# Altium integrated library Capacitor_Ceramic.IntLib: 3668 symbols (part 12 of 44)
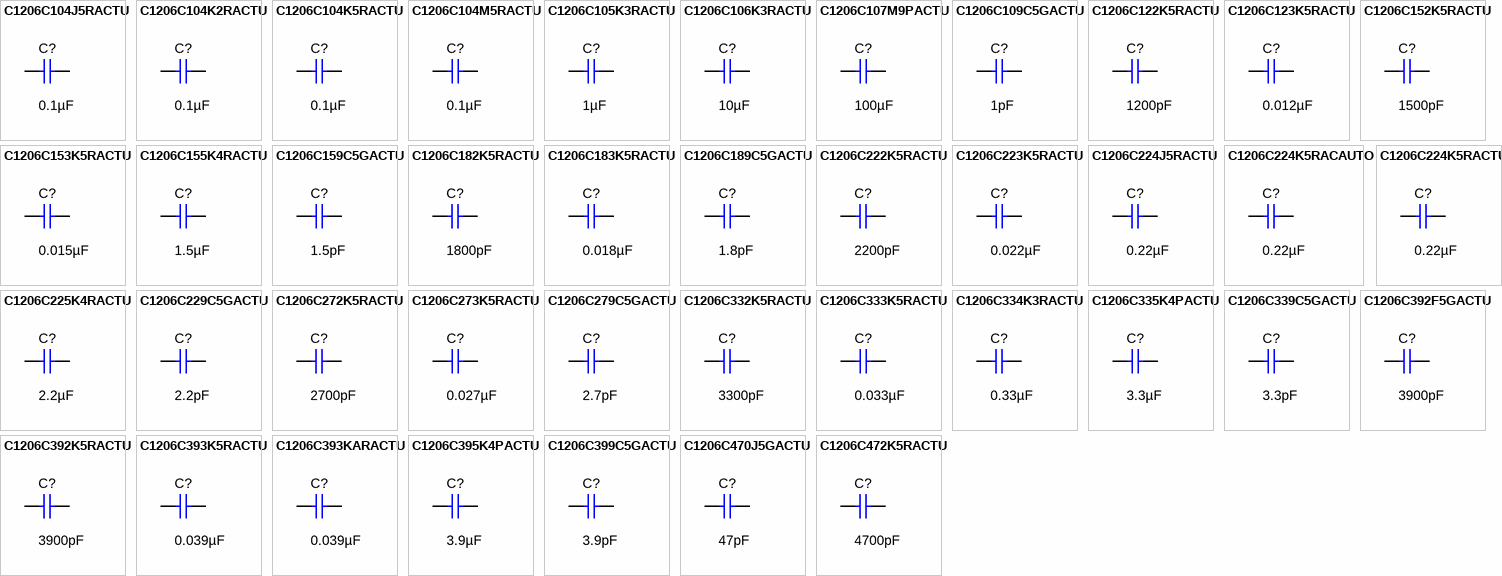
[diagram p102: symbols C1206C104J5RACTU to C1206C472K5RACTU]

## C1206C104K2RACTU
designator C?  ValueDisplayed: 0.1µF  (hidden comment: C1206C104K2RACTU)
CAP, CERM, 0.1 µF, 200 V,+/- 10%, X7R, 1206; Manufacturer: Kemet; Polarized: N; CompType: Capacitor; Value: 0.1uF; U/M: EA; Cap_F: 0.0000001; Tolerance_%: 10; VDC_V: 200; Value2: 200V; TaMin_C: -55; TaMax_C: 125; Cap_Case: 1206; SizeArea_mm2: 5.12; SizeAreaWB_mm2: 10.92; SizeX_mm: 3.2; SizeY_mm: 1.6; SizeZ_mm: 1.35; AEC Category: Q200
signal-integrity model Cap
simulation model Cap
footprint 1206
footprint 1206M
footprint 1206L
pins: 1, 2

## C1206C104K5RACTU
designator C?  ValueDisplayed: 0.1µF  (hidden comment: C1206C104K5RACTU)
CAP, CERM, 0.1 µF, 50 V,+/- 10%, X7R, 1206; Manufacturer: Kemet; Polarized: N; CompType: Capacitor; Value: 0.1uF; U/M: EA; Cap_F: 0.0000001; Tolerance_%: 10; ESR_ohm: 0.059; Value1: 0.059 ohm; VDC_V: 50; Value2: 50V; IRMS_A: 1.2; TaMin_C: -55; TaMax_C: 125; Cap_Case: 1206; SizeArea_mm2: 5.12; SizeAreaWB_mm2: 10.92; SizeX_mm: 3.2; SizeY_mm: 1.6; SizeZ_mm: 1.35; AEC Category: Q200; Green_Lifecycle: Active; Green_REACh: Passed
signal-integrity model Cap
simulation model Cap
footprint 1206
footprint 1206M
footprint 1206L
pins: 1, 2

## C1206C104M5RACTU
designator C?  ValueDisplayed: 0.1µF  (hidden comment: C1206C104M5RACTU)
CAP, CERM, 0.1 µF, 50 V,+/- 20%, X7R, 1206; Manufacturer: Kemet; Polarized: N; CompType: Capacitor; Value: 0.1uF; U/M: EA; Cap_F: 0.0000001; Tolerance_%: 20; ESR_ohm: 0.059; Value1: 0.059 ohm; VDC_V: 50; Value2: 50V; IRMS_A: 1.2; TaMin_C: -55; TaMax_C: 125; Cap_Case: 1206; SizeArea_mm2: 5.12; SizeAreaWB_mm2: 10.92; SizeX_mm: 3.2; SizeY_mm: 1.6; SizeZ_mm: 1.35; AEC Category: Q200; Green_Lifecycle: Active; Green_REACh: Passed
signal-integrity model Cap
simulation model Cap
footprint 1206
footprint 1206M
footprint 1206L
pins: 1, 2

## C1206C105K3RACTU
designator C?  ValueDisplayed: 1µF  (hidden comment: C1206C105K3RACTU)
CAP, CERM, 1 µF, 25 V,+/- 10%, X7R, 1206; Manufacturer: Kemet; Polarized: N; CompType: Capacitor; Value: 1uF; U/M: EA; Cap_F: 0.000001; Tolerance_%: 10; ESR_ohm: 0.011; Value1: 0.011 ohm; VDC_V: 25; Value2: 25V; IRMS_A: 3.55; TaMin_C: -55; TaMax_C: 125; Cap_Case: 1206; SizeArea_mm2: 5.12; SizeAreaWB_mm2: 10.92; SizeX_mm: 3.2; SizeY_mm: 1.6; SizeZ_mm: 1.35; AEC Category: Q200; Green_Lifecycle: Active; Green_REACh: Passed
signal-integrity model Cap
simulation model Cap
footprint 1206
footprint 1206M
footprint 1206L
pins: 1, 2

## C1206C106K3RACTU
designator C?  ValueDisplayed: 10µF  (hidden comment: C1206C106K3RACTU)
CAP, CERM, 10 µF, 25 V,+/- 10%, X7R, 1206; Manufacturer: Kemet; Polarized: N; CompType: Capacitor; Value: 10uF; U/M: EA; Cap_F: 0.00001; Tolerance_%: 10; VDC_V: 25; Value2: 25V; TaMin_C: -55; TaMax_C: 125; Cap_Case: 1206; SizeArea_mm2: 5.12; SizeAreaWB_mm2: 10.92; SizeX_mm: 3.2; SizeY_mm: 1.6; SizeZ_mm: 1.9; AEC Category: Q200; Green_Lifecycle: Active; Green_REACh: Passed
signal-integrity model Cap
simulation model Cap
footprint 1206_190
footprint 1206_190M
footprint 1206_190L
pins: 1, 2

## C1206C107M9PACTU
designator C?  ValueDisplayed: 100µF  (hidden comment: C1206C107M9PACTU)
CAP, CERM, 100 µF, 6.3 V,+/- 20%, X5R, 1206; Manufacturer: Kemet; Polarized: N; CompType: Capacitor; Value: 100uF; U/M: EA; Cap_F: 0.0001; Tolerance_%: 20; VDC_V: 6.3; Value2: 6.3V; TaMin_C: -55; TaMax_C: 85; Cap_Case: 1206; SizeArea_mm2: 5.12; SizeAreaWB_mm2: 10.92; SizeX_mm: 3.2; SizeY_mm: 1.6; SizeZ_mm: 1.9; AEC Category: Q200; Green_Lifecycle: Active; Green_REACh: Passed
signal-integrity model Cap
simulation model Cap
footprint 1206_190
footprint 1206_190M
footprint 1206_190L
pins: 1, 2

## C1206C109C5GACTU
designator C?  ValueDisplayed: 1pF  (hidden comment: C1206C109C5GACTU)
CAP, CERM, 1 pF, 50 V,+/- 25%, C0G/NP0, 1206; Manufacturer: Kemet; Polarized: N; CompType: Capacitor; Value: 1pF; U/M: EA; Cap_F: 0.000000000001; Tolerance_%: 25; ESR_ohm: 0.821; Value1: 0.821 ohm; VDC_V: 50; Value2: 50V; IRMS_A: 0.022; TaMin_C: -55; TaMax_C: 125; Cap_Case: 1206; SizeArea_mm2: 5.12; SizeAreaWB_mm2: 10.92; SizeX_mm: 3.2; SizeY_mm: 1.6; SizeZ_mm: 1.35; AEC Category: Q200; Green_Lifecycle: Not Set; Green_REACh: Incomplete
signal-integrity model Cap
simulation model Cap
footprint 1206
footprint 1206M
footprint 1206L
pins: 1, 2

## C1206C122K5RACTU
designator C?  ValueDisplayed: 1200pF  (hidden comment: C1206C122K5RACTU)
CAP, CERM, 1200 pF, 50 V,+/- 10%, X7R, 1206; Manufacturer: Kemet; Polarized: N; CompType: Capacitor; Value: 1200pF; U/M: EA; Cap_F: 0.0000000012; Tolerance_%: 10; ESR_ohm: 0.604; Value1: 0.604 ohm; VDC_V: 50; Value2: 50V; IRMS_A: 0.164; TaMin_C: -55; TaMax_C: 125; Cap_Case: 1206; SizeArea_mm2: 5.12; SizeAreaWB_mm2: 10.92; SizeX_mm: 3.2; SizeY_mm: 1.6; SizeZ_mm: 1.35; AEC Category: Q200; Green_Lifecycle: Not Set; Green_REACh: Incomplete
signal-integrity model Cap
simulation model Cap
footprint 1206
footprint 1206M
footprint 1206L
pins: 1, 2

## C1206C123K5RACTU
designator C?  ValueDisplayed: 0.012µF  (hidden comment: C1206C123K5RACTU)
CAP, CERM, 0.012 µF, 50 V,+/- 10%, X7R, 1206; Manufacturer: Kemet; Polarized: N; CompType: Capacitor; Value: 0.012uF; U/M: EA; Cap_F: 0.000000012; Tolerance_%: 10; ESR_ohm: 0.136; Value1: 0.136 ohm; VDC_V: 50; Value2: 50V; IRMS_A: 0.475; TaMin_C: -55; TaMax_C: 125; Cap_Case: 1206; SizeArea_mm2: 5.12; SizeAreaWB_mm2: 10.92; SizeX_mm: 3.2; SizeY_mm: 1.6; SizeZ_mm: 1.35; AEC Category: Q200; Green_Lifecycle: Not Set; Green_REACh: Incomplete
signal-integrity model Cap
simulation model Cap
footprint 1206
footprint 1206M
footprint 1206L
pins: 1, 2

## C1206C152K5RACTU
designator C?  ValueDisplayed: 1500pF  (hidden comment: C1206C152K5RACTU)
CAP, CERM, 1500 pF, 50 V,+/- 10%, X7R, 1206; Manufacturer: Kemet; Polarized: N; CompType: Capacitor; Value: 1500pF; U/M: EA; Cap_F: 0.0000000015; Tolerance_%: 10; ESR_ohm: 0.545; Value1: 0.545 ohm; VDC_V: 50; Value2: 50V; IRMS_A: 0.173; TaMin_C: -55; TaMax_C: 125; Cap_Case: 1206; SizeArea_mm2: 5.12; SizeAreaWB_mm2: 10.92; SizeX_mm: 3.2; SizeY_mm: 1.6; SizeZ_mm: 1.35; AEC Category: Q200; Green_Lifecycle: Not Set; Green_REACh: Incomplete
signal-integrity model Cap
simulation model Cap
footprint 1206
footprint 1206M
footprint 1206L
pins: 1, 2

## C1206C153K5RACTU
designator C?  ValueDisplayed: 0.015µF  (hidden comment: C1206C153K5RACTU)
CAP, CERM, 0.015 µF, 50 V,+/- 10%, X7R, 1206; Manufacturer: Kemet; Polarized: N; CompType: Capacitor; Value: 0.015uF; U/M: EA; Cap_F: 0.000000015; Tolerance_%: 10; ESR_ohm: 0.12; Value1: 0.12 ohm; VDC_V: 50; Value2: 50V; IRMS_A: 0.536; TaMin_C: -55; TaMax_C: 125; Cap_Case: 1206; SizeArea_mm2: 5.12; SizeAreaWB_mm2: 10.92; SizeX_mm: 3.2; SizeY_mm: 1.6; SizeZ_mm: 1.35; AEC Category: Q200; Green_Lifecycle: Not Set; Green_REACh: Incomplete
signal-integrity model Cap
simulation model Cap
footprint 1206
footprint 1206M
footprint 1206L
pins: 1, 2

## C1206C155K4RACTU
designator C?  ValueDisplayed: 1.5µF  (hidden comment: C1206C155K4RACTU)
CAP, CERM, 1.5 µF, 16 V,+/- 10%, X7R, 1206; Manufacturer: Kemet; Polarized: N; CompType: Capacitor; Value: 1.5uF; U/M: EA; Cap_F: 0.0000015; Tolerance_%: 10; ESR_ohm: 0.01; Value1: 0.01 ohm; VDC_V: 16; Value2: 16V; IRMS_A: 4.19; TaMin_C: -55; TaMax_C: 125; Cap_Case: 1206; SizeArea_mm2: 5.12; SizeAreaWB_mm2: 10.92; SizeX_mm: 3.2; SizeY_mm: 1.6; SizeZ_mm: 1.35; AEC Category: Q200; Green_Lifecycle: Not Set; Green_REACh: Incomplete
signal-integrity model Cap
simulation model Cap
footprint 1206
footprint 1206M
footprint 1206L
pins: 1, 2

## C1206C159C5GACTU
designator C?  ValueDisplayed: 1.5pF  (hidden comment: C1206C159C5GACTU)
CAP, CERM, 1.5 pF, 50 V,+/- 17%, C0G/NP0, 1206; Manufacturer: Kemet; Polarized: N; CompType: Capacitor; Value: 1.5pF; U/M: EA; Cap_F: 0.0000000000015; Tolerance_%: 17; ESR_ohm: 0.665; Value1: 0.665 ohm; VDC_V: 50; Value2: 50V; IRMS_A: 0.033; TaMin_C: -55; TaMax_C: 125; Cap_Case: 1206; SizeArea_mm2: 5.12; SizeAreaWB_mm2: 10.92; SizeX_mm: 3.2; SizeY_mm: 1.6; SizeZ_mm: 1.35; AEC Category: Q200; Green_Lifecycle: Not Set; Green_REACh: Incomplete
signal-integrity model Cap
simulation model Cap
footprint 1206
footprint 1206M
footprint 1206L
pins: 1, 2

## C1206C182K5RACTU
designator C?  ValueDisplayed: 1800pF  (hidden comment: C1206C182K5RACTU)
CAP, CERM, 1800 pF, 50 V,+/- 10%, X7R, 1206; Manufacturer: Kemet; Polarized: N; CompType: Capacitor; Value: 1800pF; U/M: EA; Cap_F: 0.0000000018; Tolerance_%: 10; ESR_ohm: 0.453; Value1: 0.453 ohm; VDC_V: 50; Value2: 50V; IRMS_A: 0.19; TaMin_C: -55; TaMax_C: 125; Cap_Case: 1206; SizeArea_mm2: 5.12; SizeAreaWB_mm2: 10.92; SizeX_mm: 3.2; SizeY_mm: 1.6; SizeZ_mm: 1.35; AEC Category: Q200; Green_Lifecycle: Not Set; Green_REACh: Incomplete
signal-integrity model Cap
simulation model Cap
footprint 1206
footprint 1206M
footprint 1206L
pins: 1, 2

## C1206C183K5RACTU
designator C?  ValueDisplayed: 0.018µF  (hidden comment: C1206C183K5RACTU)
CAP, CERM, 0.018 µF, 50 V,+/- 10%, X7R, 1206; Manufacturer: Kemet; Polarized: N; CompType: Capacitor; Value: 0.018uF; U/M: EA; Cap_F: 0.000000018; Tolerance_%: 10; ESR_ohm: 0.114; Value1: 0.114 ohm; VDC_V: 50; Value2: 50V; IRMS_A: 0.547; TaMin_C: -55; TaMax_C: 125; Cap_Case: 1206; SizeArea_mm2: 5.12; SizeAreaWB_mm2: 10.92; SizeX_mm: 3.2; SizeY_mm: 1.6; SizeZ_mm: 1.35; AEC Category: Q200; Green_Lifecycle: Not Set; Green_REACh: Incomplete
signal-integrity model Cap
simulation model Cap
footprint 1206
footprint 1206M
footprint 1206L
pins: 1, 2

## C1206C189C5GACTU
designator C?  ValueDisplayed: 1.8pF  (hidden comment: C1206C189C5GACTU)
CAP, CERM, 1.8 pF, 50 V,+/- 14%, C0G/NP0, 1206; Manufacturer: Kemet; Polarized: N; CompType: Capacitor; Value: 1.8pF; U/M: EA; Cap_F: 0.0000000000018; Tolerance_%: 14; ESR_ohm: 0.885; Value1: 0.885 ohm; VDC_V: 50; Value2: 50V; IRMS_A: 0.04; TaMin_C: -55; TaMax_C: 125; Cap_Case: 1206; SizeArea_mm2: 5.12; SizeAreaWB_mm2: 10.92; SizeX_mm: 3.2; SizeY_mm: 1.6; SizeZ_mm: 1.35; AEC Category: Q200; Green_Lifecycle: Not Set; Green_REACh: Incomplete
signal-integrity model Cap
simulation model Cap
footprint 1206
footprint 1206M
footprint 1206L
pins: 1, 2

## C1206C222K5RACTU
designator C?  ValueDisplayed: 2200pF  (hidden comment: C1206C222K5RACTU)
CAP, CERM, 2200 pF, 50 V,+/- 10%, X7R, 1206; Manufacturer: Kemet; Polarized: N; CompType: Capacitor; Value: 2200pF; U/M: EA; Cap_F: 0.0000000022; Tolerance_%: 10; ESR_ohm: 0.41; Value1: 0.41 ohm; VDC_V: 50; Value2: 50V; IRMS_A: 0.199; TaMin_C: -55; TaMax_C: 125; Cap_Case: 1206; SizeArea_mm2: 5.12; SizeAreaWB_mm2: 10.92; SizeX_mm: 3.2; SizeY_mm: 1.6; SizeZ_mm: 1.35; AEC Category: Q200; Green_Lifecycle: Not Set; Green_REACh: Incomplete
signal-integrity model Cap
simulation model Cap
footprint 1206
footprint 1206M
footprint 1206L
pins: 1, 2

## C1206C223K5RACTU
designator C?  ValueDisplayed: 0.022µF  (hidden comment: C1206C223K5RACTU)
CAP, CERM, 0.022 µF, 50 V,+/- 10%, X7R, 1206; Manufacturer: Kemet; Polarized: N; CompType: Capacitor; Value: 0.022uF; U/M: EA; Cap_F: 0.000000022; Tolerance_%: 10; ESR_ohm: 0.104; Value1: 0.104 ohm; VDC_V: 50; Value2: 50V; IRMS_A: 0.633; TaMin_C: -55; TaMax_C: 125; Cap_Case: 1206; SizeArea_mm2: 5.12; SizeAreaWB_mm2: 10.92; SizeX_mm: 3.2; SizeY_mm: 1.6; SizeZ_mm: 1.35; AEC Category: Q200; Green_Lifecycle: Active; Green_REACh: Passed
signal-integrity model Cap
simulation model Cap
footprint 1206
footprint 1206M
footprint 1206L
pins: 1, 2

## C1206C224J5RACTU
designator C?  ValueDisplayed: 0.22µF  (hidden comment: C1206C224J5RACTU)
CAP, CERM, 0.22 µF, 50 V,+/- 5%, X7R, 1206; Manufacturer: Kemet; Polarized: N; CompType: Capacitor; Value: 0.22uF; U/M: EA; Cap_F: 0.00000022; Tolerance_%: 5; ESR_ohm: 0.081; Value1: 0.081 ohm; VDC_V: 50; Value2: 50V; IRMS_A: 1.95; TaMin_C: -55; TaMax_C: 125; Cap_Case: 1206; SizeArea_mm2: 5.12; SizeAreaWB_mm2: 10.92; SizeX_mm: 3.2; SizeY_mm: 1.6; SizeZ_mm: 1.35; AEC Category: Q200; Green_Lifecycle: Not Set; Green_REACh: Incomplete
signal-integrity model Cap
simulation model Cap
footprint 1206
footprint 1206M
footprint 1206L
pins: 1, 2

## C1206C224K5RACAUTO
designator C?  ValueDisplayed: 0.22µF  (hidden comment: C1206C224K5RACAUTO)
CAP, CERM, 0.22 µF, 50 V,+/- 10%, X7R, AEC-Q200 Grade 1, 1206; Manufacturer: Kemet; Polarized: N; CompType: Capacitor; Value: 0.22uF; U/M: EA; Cap_F: 0.00000022; Tolerance_%: 10; VDC_V: 50; Value2: 50V; TaMin_C: -55; TaMax_C: 125; Cap_Case: 1206; SizeArea_mm2: 5.12; SizeAreaWB_mm2: 10.92; SizeX_mm: 3.2; SizeY_mm: 1.6; SizeZ_mm: 1.35; AEC Category: Q200; AEC Qualified: Y; AEC Grade: 1
signal-integrity model Cap
simulation model Cap
footprint 1206
footprint 1206M
footprint 1206L
pins: 1, 2

## C1206C224K5RACTU
designator C?  ValueDisplayed: 0.22µF  (hidden comment: C1206C224K5RACTU)
CAP, CERM, 0.22 µF, 50 V,+/- 10%, X7R, 1206; Manufacturer: Kemet; Polarized: N; CompType: Capacitor; Value: 0.22uF; U/M: EA; Cap_F: 0.00000022; Tolerance_%: 10; ESR_ohm: 0.081; Value1: 0.081 ohm; VDC_V: 50; Value2: 50V; IRMS_A: 1.95; TaMin_C: -55; TaMax_C: 125; Cap_Case: 1206; SizeArea_mm2: 5.12; SizeAreaWB_mm2: 10.92; SizeX_mm: 3.2; SizeY_mm: 1.6; SizeZ_mm: 1.35; AEC Category: Q200; Green_Lifecycle: Not Set; Green_REACh: Incomplete
signal-integrity model Cap
simulation model Cap
footprint 1206
footprint 1206M
footprint 1206L
pins: 1, 2

## C1206C225K4RACTU
designator C?  ValueDisplayed: 2.2µF  (hidden comment: C1206C225K4RACTU)
CAP, CERM, 2.2 µF, 16 V,+/- 10%, X7R, 1206; Manufacturer: Kemet; Polarized: N; CompType: Capacitor; Value: 2.2uF; U/M: EA; Cap_F: 0.0000022; Tolerance_%: 10; ESR_ohm: 0.009; Value1: 0.009 ohm; VDC_V: 16; Value2: 16V; IRMS_A: 4.46; TaMin_C: -55; TaMax_C: 125; Cap_Case: 1206; SizeArea_mm2: 5.12; SizeAreaWB_mm2: 10.92; SizeX_mm: 3.2; SizeY_mm: 1.6; SizeZ_mm: 1.35; AEC Category: Q200; Green_Lifecycle: Not Set; Green_REACh: Incomplete
signal-integrity model Cap
simulation model Cap
footprint 1206
footprint 1206M
footprint 1206L
pins: 1, 2

## C1206C229C5GACTU
designator C?  ValueDisplayed: 2.2pF  (hidden comment: C1206C229C5GACTU)
CAP, CERM, 2.2 pF, 50 V,+/- 11%, C0G/NP0, 1206; Manufacturer: Kemet; Polarized: N; CompType: Capacitor; Value: 2.2pF; U/M: EA; Cap_F: 0.0000000000022; Tolerance_%: 11; ESR_ohm: 0.546; Value1: 0.546 ohm; VDC_V: 50; Value2: 50V; IRMS_A: 0.049; TaMin_C: -55; TaMax_C: 125; Cap_Case: 1206; SizeArea_mm2: 5.12; SizeAreaWB_mm2: 10.92; SizeX_mm: 3.2; SizeY_mm: 1.6; SizeZ_mm: 1.35; AEC Category: Q200; Green_Lifecycle: Not Set; Green_REACh: Incomplete
signal-integrity model Cap
simulation model Cap
footprint 1206
footprint 1206M
footprint 1206L
pins: 1, 2

## C1206C272K5RACTU
designator C?  ValueDisplayed: 2700pF  (hidden comment: C1206C272K5RACTU)
CAP, CERM, 2700 pF, 50 V,+/- 10%, X7R, 1206; Manufacturer: Kemet; Polarized: N; CompType: Capacitor; Value: 2700pF; U/M: EA; Cap_F: 0.0000000027; Tolerance_%: 10; ESR_ohm: 0.378; Value1: 0.378 ohm; VDC_V: 50; Value2: 50V; IRMS_A: 0.232; TaMin_C: -55; TaMax_C: 125; Cap_Case: 1206; SizeArea_mm2: 5.12; SizeAreaWB_mm2: 10.92; SizeX_mm: 3.2; SizeY_mm: 1.6; SizeZ_mm: 1.35; AEC Category: Q200; Green_Lifecycle: Not Set; Green_REACh: Incomplete
signal-integrity model Cap
simulation model Cap
footprint 1206
footprint 1206M
footprint 1206L
pins: 1, 2

## C1206C273K5RACTU
designator C?  ValueDisplayed: 0.027µF  (hidden comment: C1206C273K5RACTU)
CAP, CERM, 0.027 µF, 50 V,+/- 10%, X7R, 1206; Manufacturer: Kemet; Polarized: N; CompType: Capacitor; Value: 0.027uF; U/M: EA; Cap_F: 0.000000027; Tolerance_%: 10; ESR_ohm: 0.095; Value1: 0.095 ohm; VDC_V: 50; Value2: 50V; IRMS_A: 0.765; TaMin_C: -55; TaMax_C: 125; Cap_Case: 1206; SizeArea_mm2: 5.12; SizeAreaWB_mm2: 10.92; SizeX_mm: 3.2; SizeY_mm: 1.6; SizeZ_mm: 1.35; AEC Category: Q200; Green_Lifecycle: Not Set; Green_REACh: Incomplete
signal-integrity model Cap
simulation model Cap
footprint 1206
footprint 1206M
footprint 1206L
pins: 1, 2

## C1206C279C5GACTU
designator C?  ValueDisplayed: 2.7pF  (hidden comment: C1206C279C5GACTU)
CAP, CERM, 2.7 pF, 50 V,+/- 9%, C0G/NP0, 1206; Manufacturer: Kemet; Polarized: N; CompType: Capacitor; Value: 2.7pF; U/M: EA; Cap_F: 0.0000000000027; Tolerance_%: 9; ESR_ohm: 0.492; Value1: 0.492 ohm; VDC_V: 50; Value2: 50V; IRMS_A: 0.06; TaMin_C: -55; TaMax_C: 125; Cap_Case: 1206; SizeArea_mm2: 5.12; SizeAreaWB_mm2: 10.92; SizeX_mm: 3.2; SizeY_mm: 1.6; SizeZ_mm: 1.35; AEC Category: Q200; Green_Lifecycle: Not Set; Green_REACh: Incomplete
signal-integrity model Cap
simulation model Cap
footprint 1206
footprint 1206M
footprint 1206L
pins: 1, 2

## C1206C332K5RACTU
designator C?  ValueDisplayed: 3300pF  (hidden comment: C1206C332K5RACTU)
CAP, CERM, 3300 pF, 50 V,+/- 10%, X7R, 1206; Manufacturer: Kemet; Polarized: N; CompType: Capacitor; Value: 3300pF; U/M: EA; Cap_F: 0.0000000033; Tolerance_%: 10; ESR_ohm: 0.336; Value1: 0.336 ohm; VDC_V: 50; Value2: 50V; IRMS_A: 0.27; TaMin_C: -55; TaMax_C: 125; Cap_Case: 1206; SizeArea_mm2: 5.12; SizeAreaWB_mm2: 10.92; SizeX_mm: 3.2; SizeY_mm: 1.6; SizeZ_mm: 1.35; AEC Category: Q200; Green_Lifecycle: Not Set; Green_REACh: Incomplete
signal-integrity model Cap
simulation model Cap
footprint 1206
footprint 1206M
footprint 1206L
pins: 1, 2

## C1206C333K5RACTU
designator C?  ValueDisplayed: 0.033µF  (hidden comment: C1206C333K5RACTU)
CAP, CERM, 0.033 µF, 50 V,+/- 10%, X7R, 1206; Manufacturer: Kemet; Polarized: N; CompType: Capacitor; Value: 0.033uF; U/M: EA; Cap_F: 0.000000033; Tolerance_%: 10; ESR_ohm: 0.089; Value1: 0.089 ohm; VDC_V: 50; Value2: 50V; IRMS_A: 0.822; TaMin_C: -55; TaMax_C: 125; Cap_Case: 1206; SizeArea_mm2: 5.12; SizeAreaWB_mm2: 10.92; SizeX_mm: 3.2; SizeY_mm: 1.6; SizeZ_mm: 1.35; AEC Category: Q200; Green_Lifecycle: Not Set; Green_REACh: Incomplete
signal-integrity model Cap
simulation model Cap
footprint 1206
footprint 1206M
footprint 1206L
pins: 1, 2

## C1206C334K3RACTU
designator C?  ValueDisplayed: 0.33µF  (hidden comment: C1206C334K3RACTU)
CAP, CERM, 0.33 µF, 25 V,+/- 10%, X7R, 1206; Manufacturer: Kemet; Polarized: N; CompType: Capacitor; Value: 0.33uF; U/M: EA; Cap_F: 0.00000033; Tolerance_%: 10; ESR_ohm: 0.07; Value1: 0.07 ohm; VDC_V: 25; Value2: 25V; IRMS_A: 0.905; TaMin_C: -55; TaMax_C: 125; Cap_Case: 1206; SizeArea_mm2: 5.12; SizeAreaWB_mm2: 10.92; SizeX_mm: 3.2; SizeY_mm: 1.6; SizeZ_mm: 1.35; AEC Category: Q200; Green_Lifecycle: Not Set; Green_REACh: Incomplete
signal-integrity model Cap
simulation model Cap
footprint 1206
footprint 1206M
footprint 1206L
pins: 1, 2

## C1206C335K4PACTU
designator C?  ValueDisplayed: 3.3µF  (hidden comment: C1206C335K4PACTU)
CAP, CERM, 3.3 µF, 16 V,+/- 10%, X5R, 1206; Manufacturer: Kemet; Polarized: N; CompType: Capacitor; Value: 3.3uF; U/M: EA; Cap_F: 0.0000033; Tolerance_%: 10; ESR_ohm: 0.011; Value1: 0.011 ohm; VDC_V: 16; Value2: 16V; IRMS_A: 5.25; TaMin_C: -55; TaMax_C: 85; Cap_Case: 1206; SizeArea_mm2: 5.12; SizeAreaWB_mm2: 10.92; SizeX_mm: 3.2; SizeY_mm: 1.6; SizeZ_mm: 1.35; AEC Category: Q200; Green_Lifecycle: Not Set; Green_REACh: Incomplete
signal-integrity model Cap
simulation model Cap
footprint 1206
footprint 1206M
footprint 1206L
pins: 1, 2

## C1206C339C5GACTU
designator C?  ValueDisplayed: 3.3pF  (hidden comment: C1206C339C5GACTU)
CAP, CERM, 3.3 pF, 50 V,+/- 8%, C0G/NP0, 1206; Manufacturer: Kemet; Polarized: N; CompType: Capacitor; Value: 3.3pF; U/M: EA; Cap_F: 0.0000000000033; Tolerance_%: 8; ESR_ohm: 0.444; Value1: 0.444 ohm; VDC_V: 50; Value2: 50V; IRMS_A: 0.073; TaMin_C: -55; TaMax_C: 125; Cap_Case: 1206; SizeArea_mm2: 5.12; SizeAreaWB_mm2: 10.92; SizeX_mm: 3.2; SizeY_mm: 1.6; SizeZ_mm: 1.35; AEC Category: Q200; Green_Lifecycle: Not Set; Green_REACh: Incomplete
signal-integrity model Cap
simulation model Cap
footprint 1206
footprint 1206M
footprint 1206L
pins: 1, 2

## C1206C392F5GACTU
designator C?  ValueDisplayed: 3900pF  (hidden comment: C1206C392F5GACTU)
CAP, CERM, 3900 pF, 50 V,+/- 1%, C0G/NP0, 1206; Manufacturer: Kemet; Polarized: N; CompType: Capacitor; Value: 3900pF; U/M: EA; Cap_F: 0.0000000039; Tolerance_%: 1; VDC_V: 50; Value2: 50V; TaMin_C: -55; TaMax_C: 125; Cap_Case: 1206; SizeArea_mm2: 5.12; SizeAreaWB_mm2: 10.92; SizeX_mm: 3.2; SizeY_mm: 1.6; SizeZ_mm: 1.35; AEC Category: Q200; Green_Lifecycle: Not Set; Green_REACh: Incomplete
signal-integrity model Cap
simulation model Cap
footprint 1206
footprint 1206M
footprint 1206L
pins: 1, 2

## C1206C392K5RACTU
designator C?  ValueDisplayed: 3900pF  (hidden comment: C1206C392K5RACTU)
CAP, CERM, 3900 pF, 50 V,+/- 10%, X7R, 1206; Manufacturer: Kemet; Polarized: N; CompType: Capacitor; Value: 3900pF; U/M: EA; Cap_F: 0.0000000039; Tolerance_%: 10; ESR_ohm: 0.314; Value1: 0.314 ohm; VDC_V: 50; Value2: 50V; IRMS_A: 0.3; TaMin_C: -55; TaMax_C: 125; Cap_Case: 1206; SizeArea_mm2: 5.12; SizeAreaWB_mm2: 10.92; SizeX_mm: 3.2; SizeY_mm: 1.6; SizeZ_mm: 1.35; AEC Category: Q200; Green_Lifecycle: Not Set; Green_REACh: Incomplete
signal-integrity model Cap
simulation model Cap
footprint 1206
footprint 1206M
footprint 1206L
pins: 1, 2

## C1206C393K5RACTU
designator C?  ValueDisplayed: 0.039µF  (hidden comment: C1206C393K5RACTU)
CAP, CERM, 0.039 µF, 50 V,+/- 10%, X7R, 1206; Manufacturer: Kemet; Polarized: N; CompType: Capacitor; Value: 0.039uF; U/M: EA; Cap_F: 0.000000039; Tolerance_%: 10; ESR_ohm: 0.084; Value1: 0.084 ohm; VDC_V: 50; Value2: 50V; IRMS_A: 0.925; TaMin_C: -55; TaMax_C: 125; Cap_Case: 1206; SizeArea_mm2: 5.12; SizeAreaWB_mm2: 10.92; SizeX_mm: 3.2; SizeY_mm: 1.6; SizeZ_mm: 1.35; AEC Category: Q200; Green_Lifecycle: Not Set; Green_REACh: Incomplete
signal-integrity model Cap
simulation model Cap
footprint 1206
footprint 1206M
footprint 1206L
pins: 1, 2

## C1206C393KARACTU
designator C?  ValueDisplayed: 0.039µF  (hidden comment: C1206C393KARACTU)
CAP, CERM, 0.039 µF, 250 V,+/- 10%, X7R, 1206; Manufacturer: Kemet; Polarized: N; CompType: Capacitor; Value: 0.039uF; U/M: EA; Cap_F: 0.000000039; Tolerance_%: 10; VDC_V: 250; Value2: 250V; TaMin_C: -55; TaMax_C: 125; Cap_Case: 1206; SizeArea_mm2: 5.12; SizeAreaWB_mm2: 10.92; SizeX_mm: 3.2; SizeY_mm: 1.6; SizeZ_mm: 1.35; AEC Category: Q200
signal-integrity model Cap
simulation model Cap
footprint 1206
footprint 1206M
footprint 1206L
pins: 1, 2

## C1206C395K4PACTU
designator C?  ValueDisplayed: 3.9µF  (hidden comment: C1206C395K4PACTU)
CAP, CERM, 3.9 µF, 16 V,+/- 10%, X5R, 1206; Manufacturer: Kemet; Polarized: N; CompType: Capacitor; Value: 3.9uF; U/M: EA; Cap_F: 0.0000039; Tolerance_%: 10; ESR_ohm: 0.012; Value1: 0.012 ohm; VDC_V: 16; Value2: 16V; IRMS_A: 5.05; TaMin_C: -55; TaMax_C: 85; Cap_Case: 1206; SizeArea_mm2: 5.12; SizeAreaWB_mm2: 10.92; SizeX_mm: 3.2; SizeY_mm: 1.6; SizeZ_mm: 1.35; AEC Category: Q200; Green_Lifecycle: Not Set; Green_REACh: Incomplete
signal-integrity model Cap
simulation model Cap
footprint 1206
footprint 1206M
footprint 1206L
pins: 1, 2

## C1206C399C5GACTU
designator C?  ValueDisplayed: 3.9pF  (hidden comment: C1206C399C5GACTU)
CAP, CERM, 3.9 pF, 50 V,+/- 6%, C0G/NP0, 1206; Manufacturer: Kemet; Polarized: N; CompType: Capacitor; Value: 3.9pF; U/M: EA; Cap_F: 0.0000000000039; Tolerance_%: 6; ESR_ohm: 0.407; Value1: 0.407 ohm; VDC_V: 50; Value2: 50V; IRMS_A: 0.086; TaMin_C: -55; TaMax_C: 125; Cap_Case: 1206; SizeArea_mm2: 5.12; SizeAreaWB_mm2: 10.92; SizeX_mm: 3.2; SizeY_mm: 1.6; SizeZ_mm: 1.35; AEC Category: Q200; Green_Lifecycle: Not Set; Green_REACh: Incomplete
signal-integrity model Cap
simulation model Cap
footprint 1206
footprint 1206M
footprint 1206L
pins: 1, 2

## C1206C470J5GACTU
designator C?  ValueDisplayed: 47pF  (hidden comment: C1206C470J5GACTU)
CAP, CERM, 47 pF, 50 V,+/- 5%, C0G/NP0, 1206; Manufacturer: Kemet; Polarized: N; CompType: Capacitor; Value: 47pF; U/M: EA; Cap_F: 0.000000000047; Tolerance_%: 5; VDC_V: 50; Value2: 50V; TaMin_C: -55; TaMax_C: 125; Cap_Case: 1206; SizeArea_mm2: 5.12; SizeAreaWB_mm2: 10.92; SizeX_mm: 3.2; SizeY_mm: 1.6; SizeZ_mm: 1.35; AEC Category: Q200; Green_Lifecycle: Not Set; Green_REACh: Incomplete
signal-integrity model Cap
simulation model Cap
footprint 1206
footprint 1206M
footprint 1206L
pins: 1, 2

## C1206C472K5RACTU
designator C?  ValueDisplayed: 4700pF  (hidden comment: C1206C472K5RACTU)
CAP, CERM, 4700 pF, 50 V,+/- 10%, X7R, 1206; Manufacturer: Kemet; Polarized: N; CompType: Capacitor; Value: 4700pF; U/M: EA; Cap_F: 0.0000000047; Tolerance_%: 10; ESR_ohm: 0.234; Value1: 0.234 ohm; VDC_V: 50; Value2: 50V; IRMS_A: 0.29; TaMin_C: -55; TaMax_C: 125; Cap_Case: 1206; SizeArea_mm2: 5.12; SizeAreaWB_mm2: 10.92; SizeX_mm: 3.2; SizeY_mm: 1.6; SizeZ_mm: 1.35; AEC Category: Q200; Green_Lifecycle: Active; Green_REACh: Passed
signal-integrity model Cap
simulation model Cap
footprint 1206
footprint 1206M
footprint 1206L
pins: 1, 2

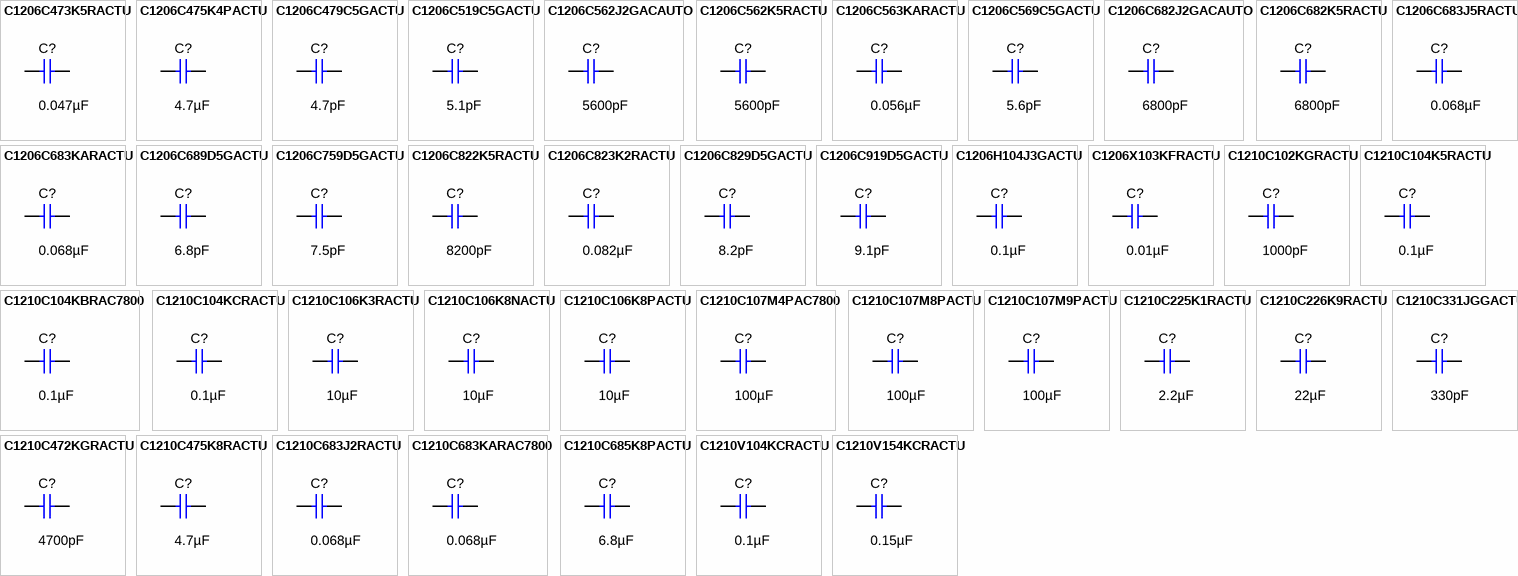
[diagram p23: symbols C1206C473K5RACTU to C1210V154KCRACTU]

## C1206C473K5RACTU
designator C?  ValueDisplayed: 0.047µF  (hidden comment: C1206C473K5RACTU)
CAP, CERM, 0.047 µF, 50 V,+/- 10%, X7R, 1206; Manufacturer: Kemet; Polarized: N; CompType: Capacitor; Value: 0.047uF; U/M: EA; Cap_F: 0.000000047; Tolerance_%: 10; ESR_ohm: 0.076; Value1: 0.076 ohm; VDC_V: 50; Value2: 50V; IRMS_A: 1.14; TaMin_C: -55; TaMax_C: 125; Cap_Case: 1206; SizeArea_mm2: 5.12; SizeAreaWB_mm2: 10.92; SizeX_mm: 3.2; SizeY_mm: 1.6; SizeZ_mm: 1.35; AEC Category: Q200; Green_Lifecycle: Not Set; Green_REACh: Incomplete
signal-integrity model Cap
simulation model Cap
footprint 1206
footprint 1206M
footprint 1206L
pins: 1, 2

## C1206C475K4PACTU
designator C?  ValueDisplayed: 4.7µF  (hidden comment: C1206C475K4PACTU)
CAP, CERM, 4.7 µF, 16 V,+/- 10%, X5R, 1206; Manufacturer: Kemet; Polarized: N; CompType: Capacitor; Value: 4.7uF; U/M: EA; Cap_F: 0.0000047; Tolerance_%: 10; ESR_ohm: 0.013; Value1: 0.013 ohm; VDC_V: 16; Value2: 16V; IRMS_A: 4.9; TaMin_C: -55; TaMax_C: 85; Cap_Case: 1206; SizeArea_mm2: 5.12; SizeAreaWB_mm2: 10.92; SizeX_mm: 3.2; SizeY_mm: 1.6; SizeZ_mm: 1.35; AEC Category: Q200; Green_Lifecycle: Active; Green_REACh: Passed
signal-integrity model Cap
simulation model Cap
footprint 1206
footprint 1206M
footprint 1206L
pins: 1, 2

## C1206C479C5GACTU
designator C?  ValueDisplayed: 4.7pF  (hidden comment: C1206C479C5GACTU)
CAP, CERM, 4.7 pF, 50 V,+/- 5%, C0G/NP0, 1206; Manufacturer: Kemet; Polarized: N; CompType: Capacitor; Value: 4.7pF; U/M: EA; Cap_F: 0.0000000000047; Tolerance_%: 5; ESR_ohm: 0.37; Value1: 0.37 ohm; VDC_V: 50; Value2: 50V; IRMS_A: 0.104; TaMin_C: -55; TaMax_C: 125; Cap_Case: 1206; SizeArea_mm2: 5.12; SizeAreaWB_mm2: 10.92; SizeX_mm: 3.2; SizeY_mm: 1.6; SizeZ_mm: 1.35; AEC Category: Q200; Green_Lifecycle: Not Set; Green_REACh: Incomplete
signal-integrity model Cap
simulation model Cap
footprint 1206
footprint 1206M
footprint 1206L
pins: 1, 2

## C1206C519C5GACTU
designator C?  ValueDisplayed: 5.1pF  (hidden comment: C1206C519C5GACTU)
CAP, CERM, 5.1 pF, 50 V,+/- 5%, C0G/NP0, 1206; Manufacturer: Kemet; Polarized: N; CompType: Capacitor; Value: 5.1pF; U/M: EA; Cap_F: 0.0000000000051; Tolerance_%: 5; ESR_ohm: 0.354; Value1: 0.354 ohm; VDC_V: 50; Value2: 50V; IRMS_A: 0.113; TaMin_C: -55; TaMax_C: 125; Cap_Case: 1206; SizeArea_mm2: 5.12; SizeAreaWB_mm2: 10.92; SizeX_mm: 3.2; SizeY_mm: 1.6; SizeZ_mm: 1.35; AEC Category: Q200; Green_Lifecycle: Not Set; Green_REACh: Incomplete
signal-integrity model Cap
simulation model Cap
footprint 1206
footprint 1206M
footprint 1206L
pins: 1, 2

## C1206C562J2GACAUTO
designator C?  ValueDisplayed: 5600pF  (hidden comment: C1206C562J2GACAUTO)
CAP, CERM, 5600 pF, 200 V,+/- 5%, C0G/NP0, AEC-Q200 Grade 1, 1206; Manufacturer: Kemet; Polarized: N; CompType: Capacitor; Value: 5600pF; U/M: EA; Cap_F: 0.0000000056; Tolerance_%: 5; VDC_V: 200; Value2: 200V; TaMin_C: -55; TaMax_C: 125; Cap_Case: 1206; SizeArea_mm2: 5.12; SizeAreaWB_mm2: 10.92; SizeX_mm: 3.2; SizeY_mm: 1.6; SizeZ_mm: 1.35; AEC Category: Q200; AEC Qualified: Y; AEC Grade: 1; Green_Lifecycle: Not Set; Green_REACh: Incomplete
signal-integrity model Cap
simulation model Cap
footprint 1206
footprint 1206M
footprint 1206L
pins: 1, 2

## C1206C562K5RACTU
designator C?  ValueDisplayed: 5600pF  (hidden comment: C1206C562K5RACTU)
CAP, CERM, 5600 pF, 50 V,+/- 10%, X7R, 1206; Manufacturer: Kemet; Polarized: N; CompType: Capacitor; Value: 5600pF; U/M: EA; Cap_F: 0.0000000056; Tolerance_%: 10; ESR_ohm: 0.221; Value1: 0.221 ohm; VDC_V: 50; Value2: 50V; IRMS_A: 0.326; TaMin_C: -55; TaMax_C: 125; Cap_Case: 1206; SizeArea_mm2: 5.12; SizeAreaWB_mm2: 10.92; SizeX_mm: 3.2; SizeY_mm: 1.6; SizeZ_mm: 1.35; AEC Category: Q200; Green_Lifecycle: Not Set; Green_REACh: Incomplete
signal-integrity model Cap
simulation model Cap
footprint 1206
footprint 1206M
footprint 1206L
pins: 1, 2

## C1206C563KARACTU
designator C?  ValueDisplayed: 0.056µF  (hidden comment: C1206C563KARACTU)
CAP, CERM, 0.056 µF, 250 V,+/- 10%, X7R, 1206; Manufacturer: Kemet; Polarized: N; CompType: Capacitor; Value: 0.056uF; U/M: EA; Cap_F: 0.000000056; Tolerance_%: 10; VDC_V: 250; Value2: 250V; TaMin_C: -55; TaMax_C: 125; Cap_Case: 1206; SizeArea_mm2: 5.12; SizeAreaWB_mm2: 10.92; SizeX_mm: 3.2; SizeY_mm: 1.6; SizeZ_mm: 1.35; AEC Category: Q200; Green_Lifecycle: Not Set; Green_REACh: Incomplete
signal-integrity model Cap
simulation model Cap
footprint 1206
footprint 1206M
footprint 1206L
pins: 1, 2

## C1206C569C5GACTU
designator C?  ValueDisplayed: 5.6pF  (hidden comment: C1206C569C5GACTU)
CAP, CERM, 5.6 pF, 50 V,+/- 4%, C0G/NP0, 1206; Manufacturer: Kemet; Polarized: N; CompType: Capacitor; Value: 5.6pF; U/M: EA; Cap_F: 0.0000000000056; Tolerance_%: 4; ESR_ohm: 0.339; Value1: 0.339 ohm; VDC_V: 50; Value2: 50V; IRMS_A: 0.123; TaMin_C: -55; TaMax_C: 125; Cap_Case: 1206; SizeArea_mm2: 5.12; SizeAreaWB_mm2: 10.92; SizeX_mm: 3.2; SizeY_mm: 1.6; SizeZ_mm: 1.35; AEC Category: Q200; Green_Lifecycle: Not Set; Green_REACh: Incomplete
signal-integrity model Cap
simulation model Cap
footprint 1206
footprint 1206M
footprint 1206L
pins: 1, 2

## C1206C682J2GACAUTO
designator C?  ValueDisplayed: 6800pF  (hidden comment: C1206C682J2GACAUTO)
CAP, CERM, 6800 pF, 200 V,+/- 5%, C0G/NP0, AEC-Q200 Grade 1, 1206; Manufacturer: Kemet; Polarized: N; CompType: Capacitor; Value: 6800pF; U/M: EA; Cap_F: 0.0000000068; Tolerance_%: 5; VDC_V: 200; Value2: 200V; TaMin_C: -55; TaMax_C: 125; Cap_Case: 1206; SizeArea_mm2: 5.12; SizeAreaWB_mm2: 10.92; SizeX_mm: 3.2; SizeY_mm: 1.6; SizeZ_mm: 1.35; AEC Category: Q200; AEC Qualified: Y; AEC Grade: 1; Green_Lifecycle: Not Set; Green_REACh: Incomplete
signal-integrity model Cap
simulation model Cap
footprint 1206
footprint 1206M
footprint 1206L
pins: 1, 2

## C1206C682K5RACTU
designator C?  ValueDisplayed: 6800pF  (hidden comment: C1206C682K5RACTU)
CAP, CERM, 6800 pF, 50 V,+/- 10%, X7R, 1206; Manufacturer: Kemet; Polarized: N; CompType: Capacitor; Value: 6800pF; U/M: EA; Cap_F: 0.0000000068; Tolerance_%: 10; ESR_ohm: 0.203; Value1: 0.203 ohm; VDC_V: 50; Value2: 50V; IRMS_A: 0.368; TaMin_C: -55; TaMax_C: 125; Cap_Case: 1206; SizeArea_mm2: 5.12; SizeAreaWB_mm2: 10.92; SizeX_mm: 3.2; SizeY_mm: 1.6; SizeZ_mm: 1.35; AEC Category: Q200; Green_Lifecycle: Not Set; Green_REACh: Incomplete
signal-integrity model Cap
simulation model Cap
footprint 1206
footprint 1206M
footprint 1206L
pins: 1, 2

## C1206C683J5RACTU
designator C?  ValueDisplayed: 0.068µF  (hidden comment: C1206C683J5RACTU)
CAP, CERM, 0.068 µF, 50 V,+/- 5%, X7R, 1206; Manufacturer: Kemet; Polarized: N; CompType: Capacitor; Value: 0.068uF; U/M: EA; Cap_F: 0.000000068; Tolerance_%: 5; ESR_ohm: 0.067; Value1: 0.067 ohm; VDC_V: 50; Value2: 50V; IRMS_A: 1.06; TaMin_C: -55; TaMax_C: 125; Cap_Case: 1206; SizeArea_mm2: 5.12; SizeAreaWB_mm2: 10.92; SizeX_mm: 3.2; SizeY_mm: 1.6; SizeZ_mm: 1.35; AEC Category: Q200; Green_Lifecycle: Not Set; Green_REACh: Incomplete
signal-integrity model Cap
simulation model Cap
footprint 1206
footprint 1206M
footprint 1206L
pins: 1, 2

## C1206C683KARACTU
designator C?  ValueDisplayed: 0.068µF  (hidden comment: C1206C683KARACTU)
CAP, CERM, 0.068 µF, 250 V,+/- 10%, X7R, 1206; Manufacturer: Kemet; Polarized: N; CompType: Capacitor; Value: 0.068uF; U/M: EA; Cap_F: 0.000000068; Tolerance_%: 10; VDC_V: 250; Value2: 250V; TaMin_C: -55; TaMax_C: 125; Cap_Case: 1206; SizeArea_mm2: 5.12; SizeAreaWB_mm2: 10.92; SizeX_mm: 3.2; SizeY_mm: 1.6; SizeZ_mm: 1.35; AEC Category: Q200; Green_Lifecycle: Not Set; Green_REACh: Incomplete
signal-integrity model Cap
simulation model Cap
footprint 1206
footprint 1206M
footprint 1206L
pins: 1, 2

## C1206C689D5GACTU
designator C?  ValueDisplayed: 6.8pF  (hidden comment: C1206C689D5GACTU)
CAP, CERM, 6.8 pF, 50 V,+/- 7%, C0G/NP0, 1206; Manufacturer: Kemet; Polarized: N; CompType: Capacitor; Value: 6.8pF; U/M: EA; Cap_F: 0.0000000000068; Tolerance_%: 7; ESR_ohm: 0.307; Value1: 0.307 ohm; VDC_V: 50; Value2: 50V; IRMS_A: 0.15; TaMin_C: -55; TaMax_C: 125; Cap_Case: 1206; SizeArea_mm2: 5.12; SizeAreaWB_mm2: 10.92; SizeX_mm: 3.2; SizeY_mm: 1.6; SizeZ_mm: 1.35; AEC Category: Q200; Green_Lifecycle: Not Set; Green_REACh: Incomplete
signal-integrity model Cap
simulation model Cap
footprint 1206
footprint 1206M
footprint 1206L
pins: 1, 2

## C1206C759D5GACTU
designator C?  ValueDisplayed: 7.5pF  (hidden comment: C1206C759D5GACTU)
CAP, CERM, 7.5 pF, 50 V,+/- 7%, C0G/NP0, 1206; Manufacturer: Kemet; Polarized: N; CompType: Capacitor; Value: 7.5pF; U/M: EA; Cap_F: 0.0000000000075; Tolerance_%: 7; ESR_ohm: 0.292; Value1: 0.292 ohm; VDC_V: 50; Value2: 50V; IRMS_A: 0.166; TaMin_C: -55; TaMax_C: 125; Cap_Case: 1206; SizeArea_mm2: 5.12; SizeAreaWB_mm2: 10.92; SizeX_mm: 3.2; SizeY_mm: 1.6; SizeZ_mm: 1.35; AEC Category: Q200; Green_Lifecycle: Not Set; Green_REACh: Incomplete
signal-integrity model Cap
simulation model Cap
footprint 1206
footprint 1206M
footprint 1206L
pins: 1, 2

## C1206C822K5RACTU
designator C?  ValueDisplayed: 8200pF  (hidden comment: C1206C822K5RACTU)
CAP, CERM, 8200 pF, 50 V,+/- 10%, X7R, 1206; Manufacturer: Kemet; Polarized: N; CompType: Capacitor; Value: 8200pF; U/M: EA; Cap_F: 0.0000000082; Tolerance_%: 10; ESR_ohm: 0.184; Value1: 0.184 ohm; VDC_V: 50; Value2: 50V; IRMS_A: 0.437; TaMin_C: -55; TaMax_C: 125; Cap_Case: 1206; SizeArea_mm2: 5.12; SizeAreaWB_mm2: 10.92; SizeX_mm: 3.2; SizeY_mm: 1.6; SizeZ_mm: 1.35; AEC Category: Q200; Green_Lifecycle: Not Set; Green_REACh: Incomplete
signal-integrity model Cap
simulation model Cap
footprint 1206
footprint 1206M
footprint 1206L
pins: 1, 2

## C1206C823K2RACTU
designator C?  ValueDisplayed: 0.082µF  (hidden comment: C1206C823K2RACTU)
CAP, CERM, 0.082 µF, 200 V,+/- 10%, X7R, 1206; Manufacturer: Kemet; Polarized: N; CompType: Capacitor; Value: 0.082uF; U/M: EA; Cap_F: 0.000000082; Tolerance_%: 10; VDC_V: 200; Value2: 200V; TaMin_C: -55; TaMax_C: 125; Cap_Case: 1206; SizeArea_mm2: 5.12; SizeAreaWB_mm2: 10.92; SizeX_mm: 3.2; SizeY_mm: 1.6; SizeZ_mm: 1.35; AEC Category: Q200
signal-integrity model Cap
simulation model Cap
footprint 1206
footprint 1206M
footprint 1206L
pins: 1, 2

## C1206C829D5GACTU
designator C?  ValueDisplayed: 8.2pF  (hidden comment: C1206C829D5GACTU)
CAP, CERM, 8.2 pF, 50 V,+/- 6%, C0G/NP0, 1206; Manufacturer: Kemet; Polarized: N; CompType: Capacitor; Value: 8.2pF; U/M: EA; Cap_F: 0.0000000000082; Tolerance_%: 6; ESR_ohm: 0.278; Value1: 0.278 ohm; VDC_V: 50; Value2: 50V; IRMS_A: 0.181; TaMin_C: -55; TaMax_C: 125; Cap_Case: 1206; SizeArea_mm2: 5.12; SizeAreaWB_mm2: 10.92; SizeX_mm: 3.2; SizeY_mm: 1.6; SizeZ_mm: 1.35; AEC Category: Q200; Green_Lifecycle: Not Set; Green_REACh: Incomplete
signal-integrity model Cap
simulation model Cap
footprint 1206
footprint 1206M
footprint 1206L
pins: 1, 2

## C1206C919D5GACTU
designator C?  ValueDisplayed: 9.1pF  (hidden comment: C1206C919D5GACTU)
CAP, CERM, 9.1 pF, 50 V,+/- 5%, C0G/NP0, 1206; Manufacturer: Kemet; Polarized: N; CompType: Capacitor; Value: 9.1pF; U/M: EA; Cap_F: 0.0000000000091; Tolerance_%: 5; ESR_ohm: 0.265; Value1: 0.265 ohm; VDC_V: 50; Value2: 50V; IRMS_A: 0.201; TaMin_C: -55; TaMax_C: 125; Cap_Case: 1206; SizeArea_mm2: 5.12; SizeAreaWB_mm2: 10.92; SizeX_mm: 3.2; SizeY_mm: 1.6; SizeZ_mm: 1.35; AEC Category: Q200; Green_Lifecycle: Not Set; Green_REACh: Incomplete
signal-integrity model Cap
simulation model Cap
footprint 1206
footprint 1206M
footprint 1206L
pins: 1, 2

## C1206H104J3GACTU
designator C?  ValueDisplayed: 0.1µF  (hidden comment: C1206H104J3GACTU)
CAP, CERM, 0.1 µF, 25 V,+/- 5%, C0G/NP0, 1206; Manufacturer: Kemet; Polarized: N; CompType: Capacitor; Value: 0.1uF; U/M: EA; Cap_F: 0.0000001; Tolerance_%: 5; VDC_V: 25; Value2: 25V; TaMin_C: -55; TaMax_C: 200; Cap_Case: 1206; SizeArea_mm2: 5.12; SizeAreaWB_mm2: 10.92; SizeX_mm: 3.2; SizeY_mm: 1.6; SizeZ_mm: 1.9; AEC Category: Q200
signal-integrity model Cap
simulation model Cap
footprint 1206_190
footprint 1206_190M
footprint 1206_190L
pins: 1, 2

## C1206X103KFRACTU
designator C?  ValueDisplayed: 0.01µF  (hidden comment: C1206X103KFRACTU)
CAP, CERM, 0.01 µF, 1500 V,+/- 10%, X7R, 1206; Manufacturer: Kemet; Polarized: N; CompType: Capacitor; Value: 0.01uF; U/M: EA; Cap_F: 0.00000001; Tolerance_%: 10; VDC_V: 1500; Value2: 1500V; TaMin_C: -55; TaMax_C: 125; Cap_Case: 1206; SizeArea_mm2: 5.12; SizeAreaWB_mm2: 10.92; SizeX_mm: 3.2; SizeY_mm: 1.6; SizeZ_mm: 1.9; AEC Category: Q200; Green_Lifecycle: Not Set; Green_REACh: Incomplete
signal-integrity model Cap
simulation model Cap
footprint 1206_190
footprint 1206_190M
footprint 1206_190L
pins: 1, 2

## C1210C102KGRACTU
designator C?  ValueDisplayed: 1000pF  (hidden comment: C1210C102KGRACTU)
CAP, CERM, 1000 pF, 2000 V,+/- 10%, X7R, 1210; Manufacturer: Kemet; Polarized: N; CompType: Capacitor; Value: 1000pF; U/M: EA; Cap_F: 0.000000001; Tolerance_%: 10; VDC_V: 2000; Value2: 2000V; TaMin_C: -55; TaMax_C: 125; Cap_Case: 1210; SizeArea_mm2: 8; SizeAreaWB_mm2: 14.7; SizeX_mm: 3.2; SizeY_mm: 2.5; SizeZ_mm: 2.7; AEC Category: Q200; Green_Lifecycle: Active; Green_REACh: Passed
signal-integrity model Cap
simulation model Cap
footprint 1210_270
footprint 1210_270M
footprint 1210_270L
pins: 1, 2

## C1210C104K5RACTU
designator C?  ValueDisplayed: 0.1µF  (hidden comment: C1210C104K5RACTU)
CAP, CERM, 0.1 µF, 50 V,+/- 10%, X7R, 1210; Manufacturer: Kemet; Polarized: N; CompType: Capacitor; Value: 0.1uF; U/M: EA; Cap_F: 0.0000001; Tolerance_%: 10; VDC_V: 50; Value2: 50V; TaMin_C: -55; TaMax_C: 125; Cap_Case: 1210; SizeArea_mm2: 8; SizeAreaWB_mm2: 14.7; SizeX_mm: 3.2; SizeY_mm: 2.5; SizeZ_mm: 1.35; AEC Category: Q200; Green_Lifecycle: Active; Green_REACh: Passed
signal-integrity model Cap
simulation model Cap
footprint 1210
footprint 1210M
footprint 1210L
pins: 1, 2

## C1210C104KBRAC7800
designator C?  ValueDisplayed: 0.1µF  (hidden comment: C1210C104KBRAC7800)
CAP, CERM, 0.1 µF, 630 V,+/- 10%, X7R, 1210; Manufacturer: Kemet; Polarized: N; CompType: Capacitor; Value: 0.1uF; U/M: EA; Cap_F: 0.0000001; Tolerance_%: 10; VDC_V: 630; Value2: 630V; TaMin_C: -55; TaMax_C: 125; Cap_Case: 1210; SizeArea_mm2: 8; SizeAreaWB_mm2: 14.7; SizeX_mm: 3.2; SizeY_mm: 2.5; SizeZ_mm: 2.8; AEC Category: Q200; Green_Lifecycle: Not Set; Green_REACh: Incomplete
signal-integrity model Cap
simulation model Cap
footprint 1210_280
pins: 1, 2

## C1210C104KCRACTU
designator C?  ValueDisplayed: 0.1µF  (hidden comment: C1210C104KCRACTU)
CAP, CERM, 0.1 µF, 500 V,+/- 10%, X7R, 1210; Manufacturer: Kemet; Polarized: N; CompType: Capacitor; Value: 0.1uF; U/M: EA; Cap_F: 0.0000001; Tolerance_%: 10; VDC_V: 500; Value2: 500V; TaMin_C: -55; TaMax_C: 125; Cap_Case: 1210; SizeArea_mm2: 8; SizeAreaWB_mm2: 14.7; SizeX_mm: 3.2; SizeY_mm: 2.5; SizeZ_mm: 2.3; AEC Category: Q200; Green_Lifecycle: Not Set; Green_REACh: Incomplete
signal-integrity model Cap
simulation model Cap
footprint 1210_230
footprint 1210_230M
footprint 1210_230L
pins: 1, 2

## C1210C106K3RACTU
designator C?  ValueDisplayed: 10µF  (hidden comment: C1210C106K3RACTU)
CAP, CERM, 10 µF, 25 V,+/- 10%, X7R, 1210; Manufacturer: Kemet; Polarized: N; CompType: Capacitor; Value: 10uF; U/M: EA; Cap_F: 0.00001; Tolerance_%: 10; VDC_V: 25; Value2: 25V; TaMin_C: -55; TaMax_C: 125; Cap_Case: 1210; SizeArea_mm2: 8; SizeAreaWB_mm2: 14.7; SizeX_mm: 3.2; SizeY_mm: 2.5; SizeZ_mm: 2.8; AEC Category: Q200
signal-integrity model Cap
simulation model Cap
footprint 1210_280
pins: 1, 2

## C1210C106K8NACTU
designator C?  ValueDisplayed: 10µF  (hidden comment: C1210C106K8NACTU)
CAP, CERM, 10 µF, 10 V,+/- 10%, X8L, 1210; Manufacturer: Kemet; Polarized: N; CompType: Capacitor; Value: 10uF; U/M: EA; Cap_F: 0.00001; Tolerance_%: 10; Value2: 10V; TaMin_C: -55; TaMax_C: 150; Cap_Case: 1210; SizeArea_mm2: 8; SizeAreaWB_mm2: 14.7; SizeX_mm: 3.2; SizeY_mm: 2.5; SizeZ_mm: 2.8; AEC Category: Q200; Green_Lifecycle: Active; Green_REACh: Passed
signal-integrity model Cap
simulation model Cap
footprint 1210_280
pins: 1, 2

## C1210C106K8PACTU
designator C?  ValueDisplayed: 10µF  (hidden comment: C1210C106K8PACTU)
CAP, CERM, 10 µF, 10 V,+/- 10%, X5R, 1210; Manufacturer: Kemet; Polarized: N; CompType: Capacitor; Value: 10uF; U/M: EA; Cap_F: 0.00001; Tolerance_%: 10; ESR_ohm: 0.008; Value1: 0.008 ohm; Value2: 10V; IRMS_A: 6.9; TaMin_C: -55; TaMax_C: 85; Cap_Case: 1210; SizeArea_mm2: 8; SizeAreaWB_mm2: 14.7; SizeX_mm: 3.2; SizeY_mm: 2.5; SizeZ_mm: 2.1; AEC Category: Q200; Green_Lifecycle: Active; Green_REACh: Passed
signal-integrity model Cap
simulation model Cap
footprint 1210_210
footprint 1210_210M
footprint 1210_210L
pins: 1, 2

## C1210C107M4PAC7800
designator C?  ValueDisplayed: 100µF  (hidden comment: C1210C107M4PAC7800)
CAP, CERM, 100 µF, 16 V,+/- 20%, X5R, 1210; Manufacturer: Kemet; Polarized: N; CompType: Capacitor; Value: 100uF; U/M: EA; Cap_F: 0.0001; Tolerance_%: 20; VDC_V: 16; Value2: 16V; TaMin_C: -55; TaMax_C: 85; Cap_Case: 1210; SizeArea_mm2: 8; SizeAreaWB_mm2: 14.7; SizeX_mm: 3.2; SizeY_mm: 2.5; SizeZ_mm: 2.7; AEC Category: Q200; Green_Lifecycle: Not Set; Green_REACh: Incomplete
signal-integrity model Cap
simulation model Cap
footprint 1210_270
footprint 1210_270M
footprint 1210_270L
pins: 1, 2

## C1210C107M8PACTU
designator C?  ValueDisplayed: 100µF  (hidden comment: C1210C107M8PACTU)
CAP, CERM, 100 µF, 10 V,+/- 20%, X5R, 1210; Manufacturer: Wurth Elektronik; Polarized: N; CompType: Capacitor; Value: 100uF; U/M: EA; Cap_F: 0.0001; Tolerance_%: 20; VDC_V: 10; Value2: 10V; TaMin_C: -55; TaMax_C: 85; Cap_Case: 1210; SizeArea_mm2: 8; SizeAreaWB_mm2: 14.7; SizeX_mm: 3.2; SizeY_mm: 2.5; SizeZ_mm: 2.8; AEC Category: Q200; Green_Lifecycle: Active; Green_REACh: Passed
signal-integrity model Cap
simulation model Cap
footprint 1210_280
pins: 1, 2

## C1210C107M9PACTU
designator C?  ValueDisplayed: 100µF  (hidden comment: C1210C107M9PACTU)
CAP, CERM, 100 µF, 6.3 V,+/- 20%, X5R, 1210; Manufacturer: Kemet; Polarized: N; CompType: Capacitor; Value: 100uF; U/M: EA; Cap_F: 0.0001; Tolerance_%: 20; VDC_V: 6.3; Value2: 6.3V; TaMin_C: -55; TaMax_C: 85; Cap_Case: 1210; SizeArea_mm2: 8; SizeAreaWB_mm2: 14.7; SizeX_mm: 3.2; SizeY_mm: 2.5; SizeZ_mm: 2.8; AEC Category: Q200; Green_Lifecycle: Active; Green_REACh: Passed
signal-integrity model Cap
simulation model Cap
footprint 1210_280
pins: 1, 2

## C1210C225K1RACTU
designator C?  ValueDisplayed: 2.2µF  (hidden comment: C1210C225K1RACTU)
CAP, CERM, 2.2 µF, 100 V,+/- 10%, X7R, 1210; Manufacturer: Kemet; Polarized: N; CompType: Capacitor; Value: 2.2uF; U/M: EA; Cap_F: 0.0000022; Tolerance_%: 10; VDC_V: 100; Value2: 100V; TaMin_C: -55; TaMax_C: 125; Cap_Case: 1210; SizeArea_mm2: 8; SizeAreaWB_mm2: 14.7; SizeX_mm: 3.2; SizeY_mm: 2.5; SizeZ_mm: 2.1; AEC Category: Q200; Green_Lifecycle: Active; Green_REACh: Passed
signal-integrity model Cap
simulation model Cap
footprint 1210_210
footprint 1210_210M
footprint 1210_210L
pins: 1, 2

## C1210C226K9RACTU
designator C?  ValueDisplayed: 22µF  (hidden comment: C1210C226K9RACTU)
CAP, CERM, 22 µF, 6.3 V,+/- 10%, X7R, 1210; Manufacturer: Kemet; Polarized: N; CompType: Capacitor; Value: 22uF; U/M: EA; Cap_F: 0.000022; Tolerance_%: 10; VDC_V: 6.3; Value2: 6.3V; TaMin_C: -55; TaMax_C: 125; Cap_Case: 1210; SizeArea_mm2: 8; SizeAreaWB_mm2: 14.7; SizeX_mm: 3.2; SizeY_mm: 2.5; SizeZ_mm: 2.8; AEC Category: Q200
signal-integrity model Cap
simulation model Cap
footprint 1210_280
pins: 1, 2

## C1210C331JGGACTU
designator C?  ValueDisplayed: 330pF  (hidden comment: C1210C331JGGACTU)
CAP, CERM, 330 pF, 2000 V,+/- 5%, C0G/NP0, 1210; Manufacturer: Kemet; Polarized: N; CompType: Capacitor; Value: 330pF; U/M: EA; Cap_F: 0.00000000033; Tolerance_%: 5; VDC_V: 2000; Value2: 2000V; TaMin_C: -55; TaMax_C: 125; Cap_Case: 1210; SizeArea_mm2: 8; SizeAreaWB_mm2: 14.7; SizeX_mm: 3.2; SizeY_mm: 2.5; SizeZ_mm: 2.3; AEC Category: Q200
signal-integrity model Cap
simulation model Cap
footprint 1210_230
footprint 1210_230M
footprint 1210_230L
pins: 1, 2

## C1210C472KGRACTU
designator C?  ValueDisplayed: 4700pF  (hidden comment: C1210C472KGRACTU)
CAP, CERM, 4700 pF, 2000 V,+/- 10%, X7R, 1210; Manufacturer: Kemet; Polarized: N; CompType: Capacitor; Value: 4700pF; U/M: EA; Cap_F: 0.0000000047; Tolerance_%: 10; VDC_V: 2000; Value2: 2000V; TaMin_C: -55; TaMax_C: 125; Cap_Case: 1210; SizeArea_mm2: 8; SizeAreaWB_mm2: 14.7; SizeX_mm: 3.2; SizeY_mm: 2.5; SizeZ_mm: 2.3; AEC Category: Q200
signal-integrity model Cap
simulation model Cap
footprint 1210_230
footprint 1210_230M
footprint 1210_230L
pins: 1, 2

## C1210C475K8RACTU
designator C?  ValueDisplayed: 4.7µF  (hidden comment: C1210C475K8RACTU)
CAP, CERM, 4.7 µF, 10 V,+/- 10%, X7R, 1210; Manufacturer: Kemet; Polarized: N; CompType: Capacitor; Value: 4.7uF; U/M: EA; Cap_F: 0.0000047; Tolerance_%: 10; Value2: 10V; TaMin_C: -55; TaMax_C: 125; Cap_Case: 1210; SizeArea_mm2: 8; SizeAreaWB_mm2: 14.7; SizeX_mm: 3.2; SizeY_mm: 2.5; SizeZ_mm: 1.35; AEC Category: Q200
signal-integrity model Cap
simulation model Cap
footprint 1210
footprint 1210M
footprint 1210L
pins: 1, 2

## C1210C683J2RACTU
designator C?  ValueDisplayed: 0.068µF  (hidden comment: C1210C683J2RACTU)
CAP, CERM, 0.068 µF, 200 V,+/- 5%, X7R, 1210; Manufacturer: Kemet; Polarized: N; CompType: Capacitor; Value: 0.068uF; U/M: EA; Cap_F: 0.000000068; Tolerance_%: 5; VDC_V: 200; Value2: 200V; TaMin_C: -55; TaMax_C: 125; Cap_Case: 1210; SizeArea_mm2: 8; SizeAreaWB_mm2: 14.7; SizeX_mm: 3.2; SizeY_mm: 2.5; SizeZ_mm: 1.35; AEC Category: Q200; Green_Lifecycle: Not Set; Green_REACh: Incomplete
signal-integrity model Cap
simulation model Cap
footprint 1210
footprint 1210M
footprint 1210L
pins: 1, 2

## C1210C683KARAC7800
designator C?  ValueDisplayed: 0.068µF  (hidden comment: C1210C683KARAC7800)
CAP, CERM, 0.068 µF, 250 V,+/- 10%, X7R, 1210; Manufacturer: Kemet; Polarized: N; CompType: Capacitor; Value: 0.068uF; U/M: EA; Cap_F: 0.000000068; Tolerance_%: 10; VDC_V: 250; Value2: 250V; TaMin_C: -55; TaMax_C: 125; Cap_Case: 1210; SizeArea_mm2: 8; SizeAreaWB_mm2: 14.7; SizeX_mm: 3.2; SizeY_mm: 2.5; SizeZ_mm: 1.35; AEC Category: Q200; Green_Lifecycle: Not Set; Green_REACh: Incomplete
signal-integrity model Cap
simulation model Cap
footprint 1210
footprint 1210M
footprint 1210L
pins: 1, 2

## C1210C685K8PACTU
designator C?  ValueDisplayed: 6.8µF  (hidden comment: C1210C685K8PACTU)
CAP, CERM, 6.8 µF, 10 V,+/- 10%, X5R, 1210; Manufacturer: Kemet; Polarized: N; CompType: Capacitor; Value: 6.8uF; U/M: EA; Cap_F: 0.0000068; Tolerance_%: 10; ESR_ohm: 0.008; Value1: 0.008 ohm; Value2: 10V; IRMS_A: 6.27; TaMin_C: -55; TaMax_C: 85; Cap_Case: 1210; SizeArea_mm2: 8; SizeAreaWB_mm2: 14.7; SizeX_mm: 3.2; SizeY_mm: 2.5; SizeZ_mm: 2.1; AEC Category: Q200; Green_Lifecycle: Not Set; Green_REACh: Incomplete
signal-integrity model Cap
simulation model Cap
footprint 1210_210
footprint 1210_210M
footprint 1210_210L
pins: 1, 2

## C1210V104KCRACTU
designator C?  ValueDisplayed: 0.1µF  (hidden comment: C1210V104KCRACTU)
CAP, CERM, 0.1 µF, 500 V,+/- 10%, X7R, 1210; Manufacturer: Kemet; Polarized: N; CompType: Capacitor; Value: 0.1uF; U/M: EA; Cap_F: 0.0000001; Tolerance_%: 10; VDC_V: 500; Value2: 500V; TaMin_C: -55; TaMax_C: 125; Cap_Case: 1210; SizeArea_mm2: 8; SizeAreaWB_mm2: 14.7; SizeX_mm: 3.2; SizeY_mm: 2.5; AEC Category: Q200; Green_Lifecycle: Not Set; Green_REACh: Incomplete
signal-integrity model Cap
simulation model Cap
footprint 1210_250
footprint 1210_250M
footprint 1210_250L
pins: 1, 2

## C1210V154KCRACTU
designator C?  ValueDisplayed: 0.15µF  (hidden comment: C1210V154KCRACTU)
CAP, CERM, 0.15 µF, 500 V,+/- 10%, X7R, 1210; Manufacturer: Kemet; Polarized: N; CompType: Capacitor; Value: 0.15uF; U/M: EA; Cap_F: 0.00000015; Tolerance_%: 10; VDC_V: 500; Value2: 500V; TaMin_C: -55; TaMax_C: 125; Cap_Case: 1210; SizeArea_mm2: 8; SizeAreaWB_mm2: 14.7; SizeX_mm: 3.2; SizeY_mm: 2.5; SizeZ_mm: 2.3; AEC Category: Q200
signal-integrity model Cap
simulation model Cap
footprint 1210_230
footprint 1210_230M
footprint 1210_230L
pins: 1, 2

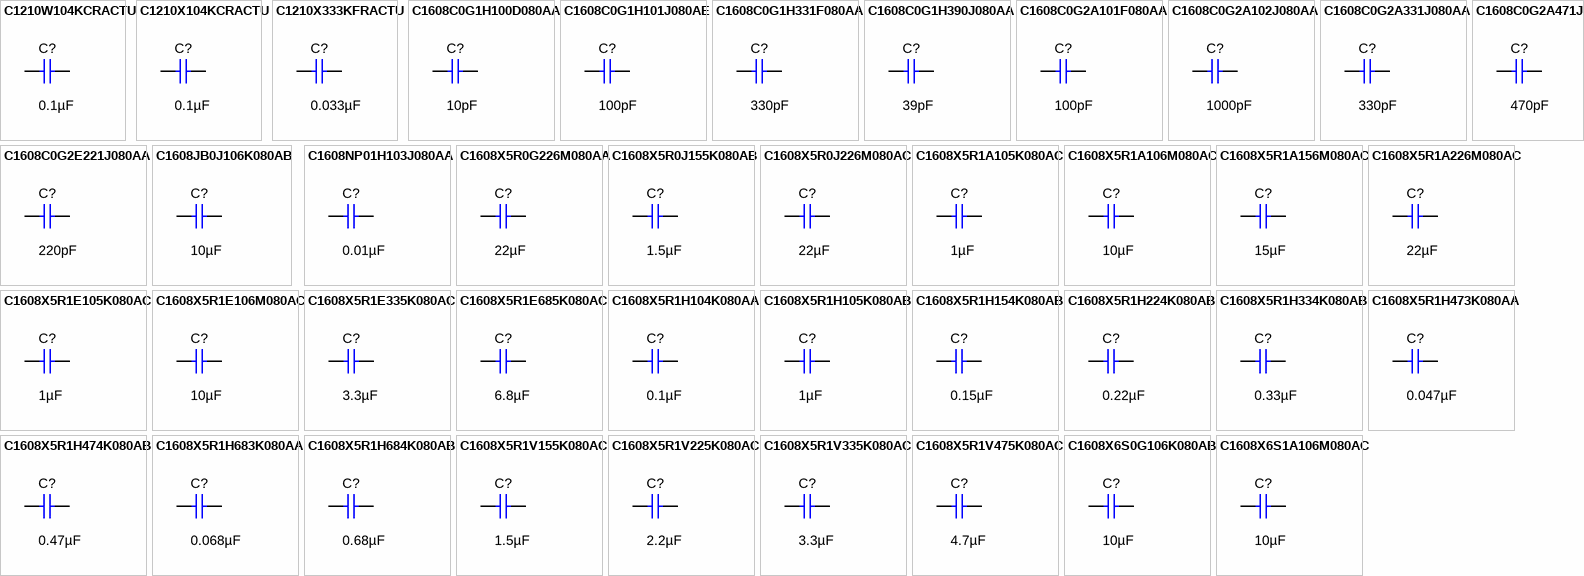
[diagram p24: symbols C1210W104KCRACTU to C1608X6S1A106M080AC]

## C1210W104KCRACTU
designator C?  ValueDisplayed: 0.1µF  (hidden comment: C1210W104KCRACTU)
CAP, CERM, 0.1 µF, 500 V,+/- 10%, X7R, 1210; Manufacturer: Kemet; Polarized: N; CompType: Capacitor; Value: 0.1uF; U/M: EA; Cap_F: 0.0000001; Tolerance_%: 10; VDC_V: 500; Value2: 500V; TaMin_C: -55; TaMax_C: 125; Cap_Case: 1210; SizeArea_mm2: 8; SizeAreaWB_mm2: 14.7; SizeX_mm: 3.2; SizeY_mm: 2.5; SizeZ_mm: 2.3; AEC Category: Q200; Green_Lifecycle: Not Set; Green_REACh: Incomplete
signal-integrity model Cap
simulation model Cap
footprint 1210_230
footprint 1210_230M
footprint 1210_230L
pins: 1, 2

## C1210X104KCRACTU
designator C?  ValueDisplayed: 0.1µF  (hidden comment: C1210X104KCRACTU)
CAP, CERM, 0.1 µF, 500 V,+/- 10%, X7R, 1210; Manufacturer: Kemet; Polarized: N; CompType: Capacitor; Value: 0.1uF; U/M: EA; Cap_F: 0.0000001; Tolerance_%: 10; VDC_V: 500; Value2: 500V; TaMin_C: -55; TaMax_C: 125; Cap_Case: 1210; SizeArea_mm2: 8; SizeAreaWB_mm2: 14.7; SizeX_mm: 3.2; SizeY_mm: 2.5; AEC Category: Q200; Green_Lifecycle: Not Set; Green_REACh: Incomplete
signal-integrity model Cap
simulation model Cap
footprint 1210_250
footprint 1210_250M
footprint 1210_250L
pins: 1, 2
